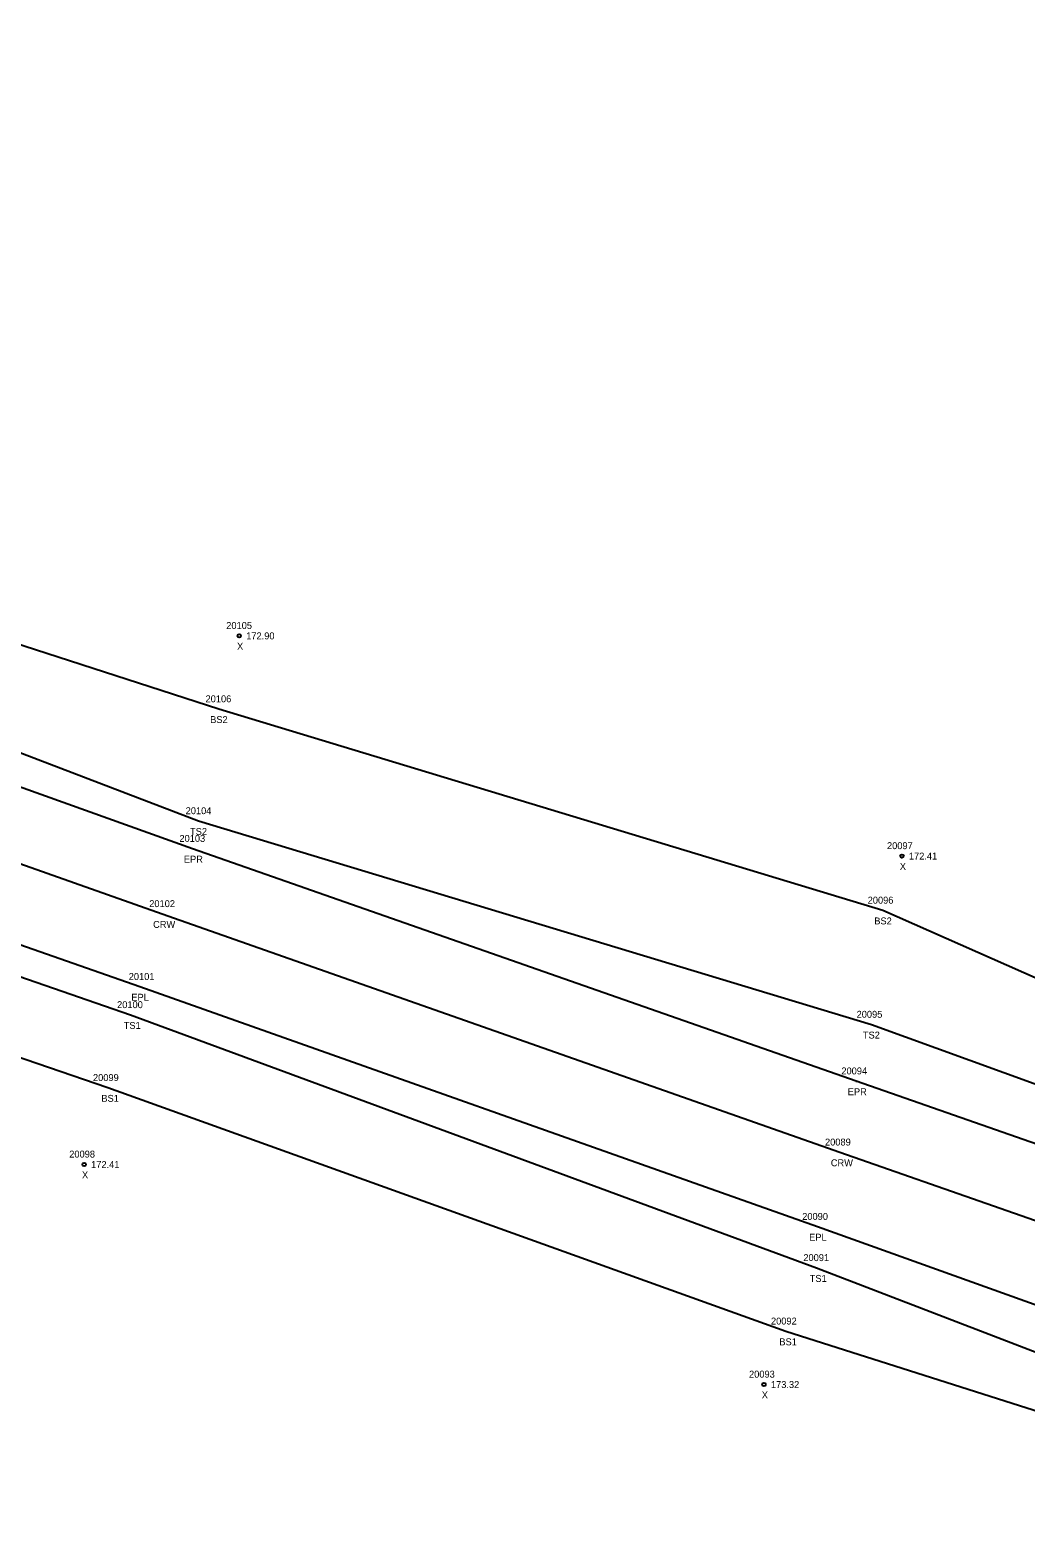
# Model space of a CAD drawing. Extents: x 2054705 to 2055845, y 756616 to 757058.
# Drawn here: x 2054988.9 to 2055132.6, y 756838.4 to 757056.1 of the extents above; entities that cross this region are included whole.
import ezdxf

# ---------------------------------------------------------------- set-up
doc = ezdxf.new("R2010")
doc.units = 0
for name, color, linetype in [('RD_DTM_BkLn1', 7, 'Continuous'), ('RD_DTM_BkLn2', 7, 'Continuous'), ('RD_EX_Road', 7, 'Continuous'), ('RD_EX_Road_txCode', 7, 'Continuous'), ('RD_Sketch8', 7, 'Continuous'), ('RD_SMD_Locator', 7, 'Continuous'), ('RD_SMD_Misc', 7, 'Continuous')]:
    doc.layers.add(name, color=color, linetype=linetype)

msp = doc.modelspace()

# ---------------------------------------------------------------- linework, layer by layer
at = {"layer": 'RD_DTM_BkLn1'}
msp.add_lwpolyline([(2055198.36, 756861.7), (2055105.78, 756894.05), (2055007.93, 756928.48), (2054913.01, 756962.02), (2054814.44, 756996.55), (2054720.09, 757029.92)], dxfattribs=at)
at = {"layer": 'RD_DTM_BkLn2'}
for points in [[(2055211.27, 756885.1), (2055111.97, 756928.98), (2055016.09, 756958.06), (2054925.03, 756987.54), (2054823.8, 757026.56), (2054727.34, 757056.13)], [(2055202.66, 756871.32), (2055205.34, 756878.01), (2055110.35, 756912.5), (2055013.19, 756941.9), (2054919.26, 756977.81), (2054820.17, 757010.81), (2054725.86, 757045.67)], [(2055194.23, 756850.45), (2055191.32, 756843.16), (2055102.38, 756877.36), (2055003.34, 756913.89), (2054907.82, 756946.94), (2054809.11, 756982.01), (2054715.58, 757014.67)], [(2055191.63, 756838.39), (2055097.99, 756868.2), (2055000.1, 756903.36), (2054903.44, 756936.48), (2054804.9, 756971.5), (2054712.86, 757006.97)]]:
    msp.add_lwpolyline(points, dxfattribs=at)
at = {"layer": 'RD_EX_Road'}
for points in [[(2055198.36, 756861.7), (2055202.66, 756871.32), (2055108.14, 756904.32), (2055012.29, 756937.9), (2054917, 756972.03), (2054818.52, 757006.44), (2054723.95, 757039.68)], [(2055198.36, 756861.7), (2055194.23, 756850.45), (2055102.54, 756883.31), (2055004.69, 756917.96), (2054909.06, 756951.44), (2054810.65, 756986.13), (2054717.55, 757018.91)]]:
    msp.add_lwpolyline(points, dxfattribs=at)
at = {"layer": 'RD_SMD_Locator'}
for centre, radius in [((2055019.06, 756968.65), 0.25), ((2055016.09, 756958.06), 0.001), ((2055013.19, 756941.9), 0.001), ((2055012.29, 756937.9), 0.001), ((2055114.74, 756936.85), 0.25), ((2055111.97, 756928.98), 0.001), ((2055007.93, 756928.48), 0.001), ((2055004.69, 756917.96), 0.001), ((2055003.34, 756913.89), 0.001), ((2055110.35, 756912.5), 0.001), ((2055000.1, 756903.36), 0.001), ((2055108.14, 756904.32), 0.001), ((2055105.78, 756894.05), 0.001), ((2054996.67, 756892.31), 0.25), ((2055102.54, 756883.31), 0.001), ((2055102.38, 756877.36), 0.001), ((2055097.99, 756868.2), 0.001), ((2055094.82, 756860.53), 0.25)]:
    msp.add_circle(centre, radius, dxfattribs=at)

# ---------------------------------------------------------------- texts
at = {"layer": 'RD_EX_Road_txCode'}
for s, p in [('20103', (2055010.42, 756938.9)), ('EPR', (2055011.06, 756935.9)), ('20101', (2055003.1, 756918.96)), ('EPL', (2055003.48, 756915.96)), ('20094', (2055105.99, 756905.32)), ('EPR', (2055106.91, 756902.32)), ('20090', (2055100.34, 756884.31)), ('EPL', (2055101.34, 756881.31))]:
    msp.add_text(s, height=1, dxfattribs=at).set_placement(p)
at = {"layer": 'RD_Sketch8'}
for s, p in [('20105', (2055017.18, 756969.65)), ('172.90', (2055020.06, 756968.15)), ('X', (2055018.74, 756966.65)), ('20097', (2055112.58, 756937.85)), ('172.41', (2055115.74, 756936.35)), ('X', (2055114.43, 756934.85)), ('20098', (2054994.51, 756893.31)), ('172.41', (2054997.67, 756891.81)), ('X', (2054996.35, 756890.31)), ('20093', (2055092.66, 756861.53)), ('X', (2055094.5, 756858.53)), ('173.32', (2055095.82, 756860.03))]:
    msp.add_text(s, height=1, dxfattribs=at).set_placement(p)
at = {"layer": 'RD_SMD_Misc'}
for s, p in [('20106', (2055014.19, 756959.06)), ('BS2', (2055014.86, 756956.06)), ('20104', (2055011.32, 756942.9)), ('TS2', (2055011.95, 756939.9)), ('20096', (2055109.79, 756929.98)), ('20102', (2055006.06, 756929.48)), ('CRW', (2055006.62, 756926.48)), ('BS2', (2055110.74, 756926.98)), ('20100', (2055001.42, 756914.89)), ('20095', (2055108.19, 756913.5)), ('TS1', (2055002.38, 756911.89)), ('TS2', (2055109.1, 756910.5)), ('20099', (2054997.94, 756904.36)), ('BS1', (2054999.15, 756901.36)), ('20089', (2055103.63, 756895.05)), ('CRW', (2055104.47, 756892.05)), ('20091', (2055100.5, 756878.36)), ('TS1', (2055101.42, 756875.36)), ('20092', (2055095.83, 756869.2)), ('BS1', (2055097.04, 756866.2))]:
    msp.add_text(s, height=1, dxfattribs=at).set_placement(p)

doc.saveas('drawing.dxf')
